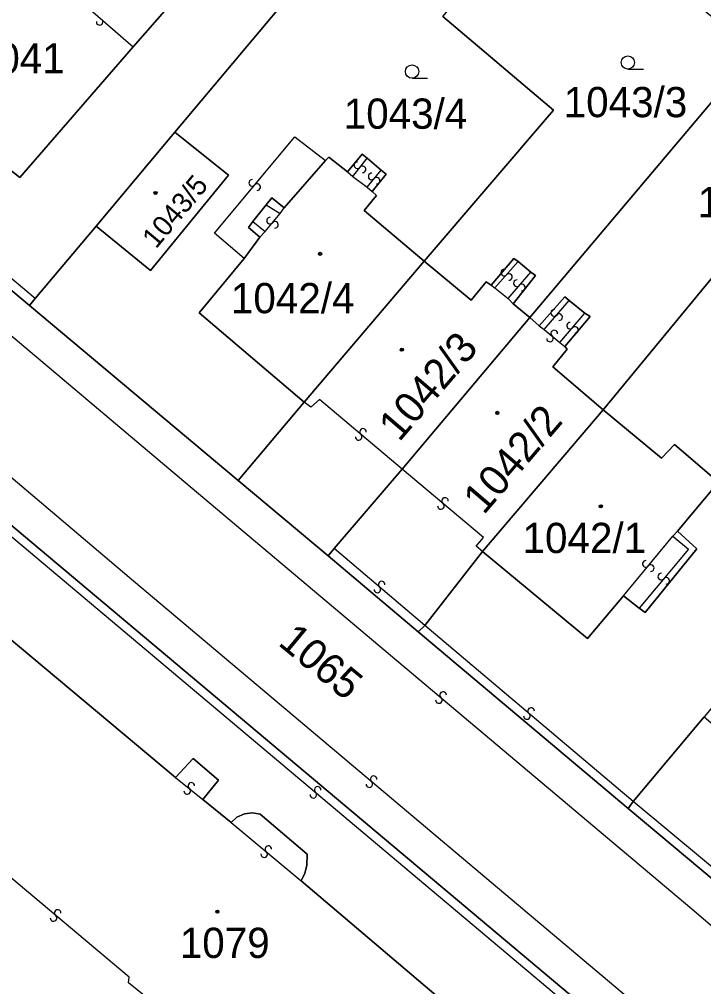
# Model space of a CAD drawing. Extents: x -600309 to -598967, y -1161267 to -1160292.
# Drawn here: x -599712.7 to -599674.2, y -1160483.6 to -1160429.2 of the extents above; entities that cross this region are included whole.
import ezdxf

# ---------------------------------------------------------------- set-up
doc = ezdxf.new("R2010")
doc.units = 0
for name, color, linetype in [('Level 1', 7, 'Continuous'), ('Level 13', 7, 'Continuous'), ('Level 3', 7, 'Continuous'), ('Level 4', 7, 'Continuous'), ('Level 5', 7, 'Continuous'), ('Level 60', 7, 'Continuous')]:
    doc.layers.add(name, color=color, linetype=linetype)

msp = doc.modelspace()

# ---------------------------------------------------------------- linework, layer by layer
at = {"layer": 'Level 1'}
for points in [[(-599689.34, -1160418.15), (-599703.97, -1160435.56)], [(-599689.94, -1160442.8), (-599682.67, -1160434.31), (-599688.89, -1160429.05), (-599682.73, -1160421.64)], [(-599710.47, -1160426.35), (-599708.2, -1160423.69), (-599703.61, -1160427.67), (-599706.31, -1160430.76)], [(-599706.31, -1160430.76), (-599712.7, -1160438.1), (-599717.06, -1160434.68), (-599716.67, -1160434.21), (-599720.46, -1160430.95), (-599720.12, -1160429.69), (-599718.92, -1160428.33)], [(-599684, -1160445.96), (-599671.51, -1160431.19)], [(-599712.15, -1160445.3), (-599726.04, -1160433.64)], [(-599708.4, -1160440.84), (-599705.34, -1160443.32), (-599700.96, -1160437.97), (-599703.97, -1160435.56)], [(-599703.97, -1160435.56), (-599708.4, -1160440.84)], [(-599697.82, -1160439.8), (-599695.49, -1160437.15)], [(-599695.49, -1160437.15), (-599695.31, -1160436.96), (-599694.25, -1160437.78)], [(-599694.25, -1160437.78), (-599693.44, -1160436.79), (-599693.16, -1160437.02)], [(-599693.16, -1160437.02), (-599692.37, -1160437.68)], [(-599692.37, -1160437.68), (-599692.08, -1160437.92), (-599692.87, -1160438.88)], [(-599698.83, -1160439.63), (-599698.52, -1160439.24), (-599697.82, -1160439.8)], [(-599692.87, -1160438.88), (-599692.63, -1160439.11), (-599693.33, -1160439.96), (-599689.94, -1160442.8)], [(-599699.58, -1160440.58), (-599698.83, -1160439.63)], [(-599679.87, -1160451.16), (-599672.83, -1160442.62), (-599667.27, -1160447.4), (-599660.99, -1160440.02)], [(-599708.4, -1160440.84), (-599711.82, -1160444.91)], [(-599699.19, -1160441.46), (-599699.83, -1160440.91), (-599699.58, -1160440.58)], [(-599700.08, -1160442.65), (-599699.19, -1160441.46)], [(-599696.7, -1160450.72), (-599702.6, -1160445.71), (-599700.08, -1160442.65)], [(-599696.7, -1160450.72), (-599689.94, -1160442.8)], [(-599689.94, -1160442.8), (-599687.3, -1160444.99), (-599686.46, -1160443.97), (-599686.18, -1160444.16)], [(-599686.18, -1160444.16), (-599684.9, -1160442.65), (-599684.65, -1160442.83)], [(-599684.65, -1160442.83), (-599683.95, -1160443.42)], [(-599683.95, -1160443.42), (-599683.68, -1160443.6), (-599684.94, -1160445.2)], [(-599711.82, -1160444.91), (-599712.15, -1160445.3)], [(-599700.41, -1160455.13), (-599712.15, -1160445.3)], [(-599684.94, -1160445.2), (-599684, -1160445.96)], [(-599683.47, -1160446.43), (-599682.04, -1160444.8), (-599681.78, -1160445.02)], [(-599681.78, -1160445.02), (-599680.9, -1160445.72)], [(-599680.9, -1160445.72), (-599680.6, -1160445.92), (-599682.04, -1160447.6)], [(-599691.18, -1160454.49), (-599684, -1160445.96)], [(-599684, -1160445.96), (-599683.47, -1160446.43)], [(-599682.04, -1160447.6), (-599681.9, -1160447.74), (-599682.71, -1160448.75), (-599679.87, -1160451.16)], [(-599700.41, -1160455.13), (-599696.7, -1160450.72)], [(-599686.66, -1160459.13), (-599679.87, -1160451.16)], [(-599679.87, -1160451.16), (-599676.59, -1160453.88), (-599675.87, -1160453.1), (-599673.38, -1160455.22), (-599675.69, -1160457.98)], [(-599695, -1160458.96), (-599691.18, -1160454.49)], [(-599695.34, -1160459.37), (-599700.41, -1160455.13)], [(-599677.73, -1160487.39), (-599713.77, -1160457.13)], [(-599675.69, -1160457.98), (-599674.6, -1160458.98), (-599677.52, -1160462.55), (-599677.86, -1160462.31)], [(-599695.34, -1160459.37), (-599695, -1160458.96)], [(-599690.28, -1160463.63), (-599695.34, -1160459.37)], [(-599686.66, -1160459.13), (-599689.91, -1160463.29)], [(-599678.74, -1160461.62), (-599680.75, -1160464.01), (-599686.66, -1160459.13)], [(-599677.86, -1160462.31), (-599678.74, -1160461.62)], [(-599689.91, -1160463.29), (-599690.28, -1160463.63)], [(-599678.47, -1160473.57), (-599690.28, -1160463.63)], [(-599713.51, -1160463.8), (-599703.93, -1160471.82)], [(-599674.2, -1160468.42), (-599678.19, -1160473.17)], [(-599703.93, -1160471.82), (-599702.95, -1160470.75), (-599701.51, -1160471.98), (-599702.39, -1160473.06)], [(-599702.39, -1160473.06), (-599700.8, -1160474.35)], [(-599678.19, -1160473.17), (-599678.47, -1160473.57)], [(-599667.06, -1160483.11), (-599678.47, -1160473.57)], [(-599700.8, -1160474.35), (-599700.48, -1160474.06), (-599700.05, -1160473.87), (-599699.6, -1160473.81), (-599699.18, -1160473.88), (-599696.52, -1160476.14), (-599696.54, -1160476.78), (-599696.66, -1160477.21), (-599696.86, -1160477.63)], [(-599696.86, -1160477.63), (-599684.42, -1160488.2)]]:
    msp.add_lwpolyline(points, dxfattribs=at)
at = {"layer": 'Level 13'}
for centre, start, end in [((-599708.201, -1160429.348), 176.1212, 48.7112), ((-599693.705, -1160437.416), 89.6146, 321.7126), ((-599693.415, -1160437.643), 269.4001, 141.9901), ((-599699.621, -1160438.401), 87.5567, 319.6547), ((-599692.901, -1160438.041), 87.9212, 320.0192), ((-599692.618, -1160438.278), 267.7067, 140.2967), ((-599699.339, -1160438.638), 267.3423, 139.9323), ((-599698.62, -1160440.52), 87.2893, 319.3873), ((-599698.34, -1160440.759), 267.0748, 139.6648), ((-599685.446, -1160443.445), 85.4283, 317.5263), ((-599685.174, -1160443.694), 265.2139, 137.8039), ((-599684.729, -1160444.039), 86.7082, 318.8062), ((-599684.451, -1160444.281), 266.4937, 139.0837), ((-599682.628, -1160445.708), 86.3374, 318.4354), ((-599682.352, -1160445.951), 266.1229, 138.7129), ((-599681.739, -1160446.429), 87.0282, 319.1262), ((-599682.63, -1160446.87), 357.312, 229.4099), ((-599681.46, -1160446.67), 266.8138, 139.4038), ((-599682.869, -1160447.15), 177.0975, 49.6875), ((-599693.391, -1160452.4), 357.1598, 229.7498), ((-599693.63, -1160452.68), 177.3742, 49.4722), ((-599688.771, -1160456.28), 357.1075, 229.6975), ((-599689.01, -1160456.56), 177.3219, 49.4199), ((-599677.481, -1160459.821), 87.6679, 319.7659), ((-599677.199, -1160460.058), 267.4535, 140.0435), ((-599676.61, -1160460.531), 87.1159, 319.7059), ((-599692.34, -1160460.98), 356.7709, 229.3609), ((-599676.33, -1160460.77), 267.3303, 139.4283), ((-599692.581, -1160461.259), 176.9853, 49.0833), ((-599688.88, -1160467.19), 357.3006, 229.3986), ((-599689.119, -1160467.47), 177.0861, 49.6761), ((-599683.931, -1160468.09), 357.0273, 229.6173), ((-599684.17, -1160468.37), 177.2417, 49.3397), ((-599692.791, -1160471.92), 357.0645, 229.6545), ((-599703.276, -1160472.583), 178.3174, 50.9074), ((-599703.043, -1160472.297), 358.5319, 230.6299), ((-599695.94, -1160472.52), 357.3291, 229.4271), ((-599693.03, -1160472.2), 177.2789, 49.3769), ((-599696.179, -1160472.8), 177.1146, 49.7046), ((-599698.711, -1160475.849), 357.5958, 229.6938), ((-599698.948, -1160476.131), 177.3813, 49.9713), ((-599710.561, -1160479.439), 357.2371, 229.8271), ((-599710.8, -1160479.72), 177.4515, 49.5495)]:
    msp.add_arc(centre, 0.184, start, end, dxfattribs=at)
at = {"layer": 'Level 3'}
for points in [[(-599711.82, -1160444.91), (-599725.59, -1160433.35), (-599726.12, -1160432.45), (-599726.41, -1160431.38), (-599726.43, -1160430.34), (-599726.26, -1160429.38), (-599723.59, -1160424.15), (-599722.92, -1160423.98), (-599723.3, -1160423.62), (-599724.03, -1160423.89)], [(-599710.47, -1160426.35), (-599709.45, -1160427.22), (-599709.86, -1160427.67), (-599706.31, -1160430.76)], [(-599618.91, -1160568.02), (-599619.16, -1160567.29), (-599622.34, -1160555.16), (-599625.26, -1160547.25), (-599628.18, -1160540.65), (-599631.35, -1160534.5), (-599633.42, -1160530.64), (-599636.09, -1160526.6), (-599652, -1160506.82), (-599658.62, -1160500.9), (-599679.28, -1160483.53), (-599706.54, -1160460.58), (-599731.82, -1160439.18), (-599735.29, -1160436.73), (-599737.13, -1160435.53), (-599739.08, -1160434.53), (-599743.68, -1160432.59), (-599750.38, -1160430.87), (-599755.47, -1160430.14), (-599762.83, -1160429.89), (-599767.01, -1160430.16), (-599768.21, -1160430.49), (-599769.35, -1160431.06)], [(-599729.02, -1160431.68), (-599728.77, -1160432.68), (-599728.36, -1160433.63), (-599727.69, -1160434.62), (-599726.98, -1160435.38), (-599725.57, -1160436.55), (-599703.11, -1160455.46), (-599674.89, -1160479.2), (-599647.66, -1160502.51), (-599631.14, -1160523.08), (-599628.28, -1160527.12), (-599625.77, -1160531.56), (-599623.17, -1160537.02), (-599619.52, -1160545.2), (-599616.01, -1160556.36), (-599613.45, -1160564.47), (-599612.9, -1160565.98)], [(-599700.08, -1160442.65), (-599701.74, -1160441.23), (-599697.23, -1160435.82), (-599695.49, -1160437.15)], [(-599693.95, -1160438.04), (-599693.16, -1160437.02)], [(-599693.16, -1160438.64), (-599692.37, -1160437.68)], [(-599694.25, -1160437.78), (-599693.95, -1160438.04)], [(-599693.95, -1160438.04), (-599693.16, -1160438.64)], [(-599693.16, -1160438.64), (-599692.87, -1160438.88)], [(-599698.83, -1160439.63), (-599698.05, -1160440.13)], [(-599698.05, -1160440.13), (-599697.82, -1160439.8)], [(-599698.9, -1160441.14), (-599698.05, -1160440.13)], [(-599699.58, -1160440.58), (-599698.9, -1160441.14)], [(-599699.19, -1160441.46), (-599698.9, -1160441.14)], [(-599685.98, -1160444.31), (-599684.65, -1160442.83)], [(-599685.23, -1160444.91), (-599683.95, -1160443.42)], [(-599686.18, -1160444.16), (-599685.98, -1160444.31)], [(-599685.98, -1160444.31), (-599685.23, -1160444.91)], [(-599685.23, -1160444.91), (-599684.94, -1160445.2)], [(-599683.19, -1160446.64), (-599681.78, -1160445.02)], [(-599682.31, -1160447.38), (-599680.9, -1160445.72)], [(-599683.47, -1160446.43), (-599683.19, -1160446.64)], [(-599683.19, -1160446.64), (-599682.31, -1160447.38)], [(-599682.31, -1160447.38), (-599682.04, -1160447.6)], [(-599691.18, -1160454.49), (-599695.84, -1160450.58), (-599696.32, -1160451.01), (-599696.7, -1160450.72)], [(-599686.66, -1160459.13), (-599687.02, -1160458.82), (-599686.6, -1160458.34), (-599691.18, -1160454.49)], [(-599714.11, -1160457.49), (-599678.02, -1160487.82)], [(-599678.74, -1160461.62), (-599675.95, -1160458.26)], [(-599675.95, -1160458.26), (-599675.07, -1160458.99), (-599677.86, -1160462.31)], [(-599675.95, -1160458.26), (-599675.69, -1160457.98)], [(-599689.91, -1160463.29), (-599695, -1160458.96)], [(-599678.19, -1160473.17), (-599689.91, -1160463.29)], [(-599703.93, -1160471.82), (-599702.39, -1160473.06)], [(-599666.71, -1160482.72), (-599678.19, -1160473.17)], [(-599700.8, -1160474.35), (-599696.86, -1160477.63)], [(-599696.07, -1160493.57), (-599697.02, -1160492.79), (-599696.24, -1160491.76), (-599704.4, -1160484.84), (-599704.73, -1160484.87), (-599706.58, -1160483.36), (-599706.54, -1160483.04), (-599714.81, -1160476.12), (-599715.66, -1160477.09), (-599716.65, -1160476.29)]]:
    msp.add_lwpolyline(points, dxfattribs=at)
at = {"layer": 'Level 5'}
for p, q in [((-599678.49, -1160432.01), (-599677.615, -1160432.01)), ((-599690.63, -1160432.52), (-599689.755, -1160432.52))]:
    msp.add_line(p, q, dxfattribs=at)
for centre, radius in [((-599678.49, -1160431.635), 0.375), ((-599690.63, -1160432.145), 0.375), ((-599705.06, -1160438.97), 0.09), ((-599705.06, -1160438.97), 0.0521), ((-599695.8, -1160442.39), 0.09), ((-599695.8, -1160442.39), 0.0521), ((-599691.2, -1160447.78), 0.09), ((-599691.2, -1160447.78), 0.0521), ((-599685.83, -1160451.33), 0.09), ((-599685.83, -1160451.33), 0.0521), ((-599680.01, -1160456.58), 0.09), ((-599680.01, -1160456.58), 0.0521), ((-599701.58, -1160479.37), 0.09), ((-599701.58, -1160479.37), 0.0521)]:
    msp.add_circle(centre, radius, dxfattribs=at)
at = {"layer": 'Level 60'}
for points in [[(-599716.05, -1160407.17), (-599715.55, -1160407.4), (-599689.34, -1160418.15), (-599703.97, -1160435.56), (-599708.4, -1160440.84), (-599711.82, -1160444.91), (-599712.15, -1160445.3), (-599726.04, -1160433.64), (-599726.6, -1160432.64), (-599726.87, -1160431.62), (-599726.96, -1160430.74), (-599726.88, -1160429.94), (-599726.69, -1160429.15), (-599724.03, -1160423.89), (-599722.8, -1160421.55), (-599719.24, -1160414)], [(-599687.3, -1160444.99), (-599689.94, -1160442.8), (-599682.67, -1160434.31), (-599688.89, -1160429.05), (-599682.73, -1160421.64), (-599681.88, -1160422.32), (-599679.79, -1160424.13), (-599673.83, -1160428.99), (-599671.51, -1160431.19), (-599684, -1160445.96), (-599684.94, -1160445.2), (-599683.68, -1160443.6), (-599683.95, -1160443.42), (-599684.65, -1160442.83), (-599684.9, -1160442.65), (-599686.18, -1160444.16), (-599686.46, -1160443.97)], [(-599717.06, -1160434.68), (-599716.67, -1160434.21), (-599720.46, -1160430.95), (-599720.12, -1160429.69), (-599718.92, -1160428.33), (-599720.31, -1160427.1), (-599719.95, -1160426.68), (-599718.94, -1160425.57), (-599718.58, -1160425.14), (-599717.16, -1160426.33), (-599716.43, -1160425.46), (-599716.07, -1160425.48), (-599714.14, -1160423.32), (-599710.47, -1160426.35), (-599708.2, -1160423.69), (-599703.61, -1160427.67), (-599706.31, -1160430.76), (-599712.7, -1160438.1)], [(-599716.67, -1160434.21), (-599717.06, -1160434.68), (-599712.7, -1160438.1), (-599706.31, -1160430.76), (-599703.61, -1160427.67), (-599708.2, -1160423.69), (-599710.47, -1160426.35), (-599714.14, -1160423.32), (-599716.07, -1160425.48), (-599716.43, -1160425.46), (-599717.16, -1160426.33), (-599718.58, -1160425.14), (-599718.94, -1160425.57), (-599719.95, -1160426.68), (-599720.31, -1160427.1), (-599718.92, -1160428.33), (-599720.12, -1160429.69), (-599720.46, -1160430.95)], [(-599683.47, -1160446.43), (-599684, -1160445.96), (-599671.51, -1160431.19), (-599663.05, -1160438.23), (-599660.99, -1160440.02), (-599667.27, -1160447.4), (-599672.83, -1160442.62), (-599679.87, -1160451.16), (-599682.71, -1160448.75), (-599681.9, -1160447.74), (-599682.04, -1160447.6), (-599680.6, -1160445.92), (-599680.9, -1160445.72), (-599681.78, -1160445.02), (-599682.04, -1160444.8)], [(-599705.34, -1160443.32), (-599708.4, -1160440.84), (-599703.97, -1160435.56), (-599700.96, -1160437.97)], [(-599689.94, -1160442.8), (-599696.7, -1160450.72), (-599702.6, -1160445.71), (-599700.08, -1160442.65), (-599699.19, -1160441.46), (-599699.83, -1160440.91), (-599699.58, -1160440.58), (-599698.83, -1160439.63), (-599698.52, -1160439.24), (-599697.82, -1160439.8), (-599695.49, -1160437.15), (-599695.31, -1160436.96), (-599694.25, -1160437.78), (-599693.44, -1160436.79), (-599693.16, -1160437.02), (-599692.37, -1160437.68), (-599692.08, -1160437.92), (-599692.87, -1160438.88), (-599692.63, -1160439.11), (-599693.33, -1160439.96)], [(-599676.59, -1160453.88), (-599679.87, -1160451.16), (-599672.83, -1160442.62), (-599667.27, -1160447.4), (-599660.99, -1160440.02), (-599654.87, -1160445.22), (-599663.37, -1160455.46), (-599668.17, -1160461.24), (-599674.2, -1160468.42), (-599678.19, -1160473.17), (-599678.47, -1160473.57), (-599690.28, -1160463.63), (-599689.91, -1160463.29), (-599686.66, -1160459.13), (-599680.75, -1160464.01), (-599678.74, -1160461.62), (-599677.86, -1160462.31), (-599677.52, -1160462.55), (-599674.6, -1160458.98), (-599675.69, -1160457.98), (-599673.38, -1160455.22), (-599675.87, -1160453.1)], [(-599695, -1160458.96), (-599695.34, -1160459.37), (-599700.41, -1160455.13), (-599696.7, -1160450.72), (-599689.94, -1160442.8), (-599687.3, -1160444.99), (-599686.46, -1160443.97), (-599686.18, -1160444.16), (-599684.9, -1160442.65), (-599684.65, -1160442.83), (-599683.95, -1160443.42), (-599683.68, -1160443.6), (-599684.94, -1160445.2), (-599684, -1160445.96), (-599691.18, -1160454.49)], [(-599679.87, -1160451.16), (-599686.66, -1160459.13), (-599689.91, -1160463.29), (-599690.28, -1160463.63), (-599695.34, -1160459.37), (-599695, -1160458.96), (-599691.18, -1160454.49), (-599684, -1160445.96), (-599683.47, -1160446.43), (-599682.04, -1160444.8), (-599681.78, -1160445.02), (-599680.9, -1160445.72), (-599680.6, -1160445.92), (-599682.04, -1160447.6), (-599681.9, -1160447.74), (-599682.71, -1160448.75)], [(-599678.47, -1160473.57), (-599678.19, -1160473.17), (-599674.2, -1160468.42), (-599671.64, -1160470.59), (-599665.99, -1160463.74), (-599664.89, -1160464.65), (-599659.77, -1160458.29), (-599663.37, -1160455.46), (-599654.87, -1160445.22), (-599651.62, -1160447.89), (-599645.87, -1160452.76), (-599644.79, -1160453.68), (-599643.4, -1160454.87), (-599657.06, -1160471.15), (-599663.22, -1160466.09), (-599663.78, -1160466.75), (-599665.36, -1160465.42), (-599669.18, -1160469.95), (-599667.63, -1160471.27), (-599669.64, -1160473.62), (-599663.33, -1160478.7), (-599666.71, -1160482.72), (-599667.06, -1160483.11)], [(-599679.87, -1160451.16), (-599676.59, -1160453.88), (-599675.87, -1160453.1), (-599673.38, -1160455.22), (-599675.69, -1160457.98), (-599674.6, -1160458.98), (-599677.52, -1160462.55), (-599677.86, -1160462.31), (-599678.74, -1160461.62), (-599680.75, -1160464.01), (-599686.66, -1160459.13)], [(-599727.52, -1160473.47), (-599716.95, -1160460.92), (-599713.51, -1160463.8), (-599703.93, -1160471.82), (-599702.95, -1160470.75), (-599701.51, -1160471.98), (-599702.39, -1160473.06), (-599700.8, -1160474.35), (-599700.48, -1160474.06), (-599700.05, -1160473.87), (-599699.6, -1160473.81), (-599699.18, -1160473.88), (-599696.52, -1160476.14), (-599696.54, -1160476.78), (-599696.66, -1160477.21), (-599696.86, -1160477.63), (-599684.42, -1160488.2), (-599683.45, -1160489.03), (-599694.15, -1160501.76)]]:
    msp.add_lwpolyline(points, close=True, dxfattribs=at)
for points in [[(-599688.89, -1160429.05), (-599682.67, -1160434.31), (-599689.94, -1160442.8), (-599693.33, -1160439.96), (-599692.63, -1160439.11), (-599692.87, -1160438.88), (-599692.08, -1160437.92), (-599692.37, -1160437.68), (-599693.16, -1160437.02), (-599693.44, -1160436.79), (-599694.25, -1160437.78), (-599695.31, -1160436.96), (-599695.49, -1160437.15), (-599697.82, -1160439.8), (-599698.52, -1160439.24), (-599698.83, -1160439.63), (-599699.58, -1160440.58), (-599699.83, -1160440.91), (-599699.19, -1160441.46), (-599700.08, -1160442.65), (-599702.6, -1160445.71), (-599696.7, -1160450.72), (-599700.41, -1160455.13), (-599712.15, -1160445.3), (-599711.82, -1160444.91), (-599708.4, -1160440.84), (-599705.34, -1160443.32), (-599700.96, -1160437.97), (-599703.97, -1160435.56), (-599689.34, -1160418.15)], [(-599671.54, -1160492.49), (-599676.09, -1160488.69), (-599677.73, -1160487.39), (-599713.77, -1160457.13), (-599734.75, -1160439.34), (-599738.52, -1160436.94), (-599743.68, -1160434.72), (-599749.32, -1160433.01), (-599754.53, -1160431.98), (-599760.11, -1160431.55), (-599764.86, -1160431.87), (-599767.37, -1160432.32), (-599768.09, -1160432.77), (-599768.65, -1160433.46), (-599769, -1160434.23), (-599769.09, -1160435.15), (-599769.35, -1160431.06), (-599769.8, -1160423.87)], [(-599734.94, -1160427.81), (-599729.02, -1160431.68), (-599726.04, -1160433.64), (-599712.15, -1160445.3), (-599700.41, -1160455.13), (-599695.34, -1160459.37), (-599690.28, -1160463.63), (-599678.47, -1160473.57), (-599667.06, -1160483.11)], [(-599684.42, -1160488.2), (-599696.86, -1160477.63), (-599696.66, -1160477.21), (-599696.54, -1160476.78), (-599696.52, -1160476.14), (-599699.18, -1160473.88), (-599699.6, -1160473.81), (-599700.05, -1160473.87), (-599700.48, -1160474.06), (-599700.8, -1160474.35), (-599702.39, -1160473.06), (-599701.51, -1160471.98), (-599702.95, -1160470.75), (-599703.93, -1160471.82), (-599713.51, -1160463.8), (-599716.95, -1160460.92), (-599714.11, -1160457.49), (-599713.77, -1160457.13), (-599677.73, -1160487.39)]]:
    msp.add_lwpolyline(points, dxfattribs=at)

# ---------------------------------------------------------------- texts
at = {"layer": 'Level 4'}
for s, p in [('1041', (-599715.222, -1160432.25)), ('1043/3', (-599682.098, -1160434.71)), ('1043/4', (-599694.471, -1160435.36)), ('1043/2', (-599674.556, -1160440.33)), ('1042/4', (-599700.819, -1160445.73)), ('1042/1', (-599684.412, -1160459.21)), ('1079', (-599703.693, -1160481.97))]:
    msp.add_text(s, height=1.7, dxfattribs=at).set_placement(p)
for s, height, rotation, p in [('1043/5', 1.14, 50.1, (-599705.03, -1160442.15)), ('1042/3', 1.7, 49.5, (-599691.35, -1160453.008)), ('1042/2', 1.7, 49.5, (-599686.593, -1160457.109)), ('1065', 1.7, 320.4, (-599698.221, -1160464.338))]:
    msp.add_text(s, height=height, rotation=rotation, dxfattribs=at).set_placement(p)

doc.saveas('drawing.dxf')
